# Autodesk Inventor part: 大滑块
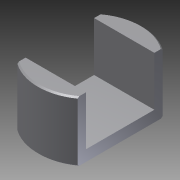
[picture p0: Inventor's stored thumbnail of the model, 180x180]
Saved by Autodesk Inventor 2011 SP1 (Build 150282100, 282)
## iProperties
Created: 2013-12
Part Number: 大滑块
Document SubType Name: Modeling
Designer: Administrator
Density: 1 g/cm^3
Author: Administrator
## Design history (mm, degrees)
sketch "草图1"
  geometry: L1 (11, 15.492)-(11, -15.492); L2 (-11, -15.492)-(-11, 15.492); A1 r 19 centre (0, 0) between (-11, -15.492) and (11, -15.492); A2 r 19 centre (0, 0) between (11, 15.492) and (-11, 15.492); 3 further points
  constraints: 4 end point, 4 point on circle, 2 centre point, 1 coincident, 1 horizontal alignment, 1 parallel, 1 vertical alignment
  dimensions: "d1" = 22 distance between parallel lines of L1 L2; "d3" = 19 distance of A1.centre point (0, 19)
extrude "拉伸1" new body sketch "草图1" distance "d4" = 22; taper "d5" = 0 deg
sketch "草图2"
  geometry: L1 (-21.946, 12.5)-(21.946, 12.5); L2 (21.946, 12.5)-(21.946, -12.5); L3 (21.946, -12.5)-(-21.946, -12.5); L4 (-21.946, -12.5)-(-21.946, 12.5); A1 r 19 centre (0, 0) between (11, 15.492) and (-11, 15.492) reference; 2 further points
  constraints: 8 end point, 2 midpoint, 2 parallel, 1 horizontal, 1 horizontal alignment, 1 perpendicular, 1 vertical alignment
  dimensions: "d6" = 43.89178 distance of L1.start L1.end; "d7" = 25 distance of L3.end L1.start
extrude "拉伸2" cut sketch "草图2" distance "d8" = 18; taper "d9" = 0 deg
chamfer "倒角1" distance "d10" = 0.5; stored, may be unused: second distance "d11" = 2, angle "d12" = 45 deg
node "实体1"
other parameters: "d0" = 38
